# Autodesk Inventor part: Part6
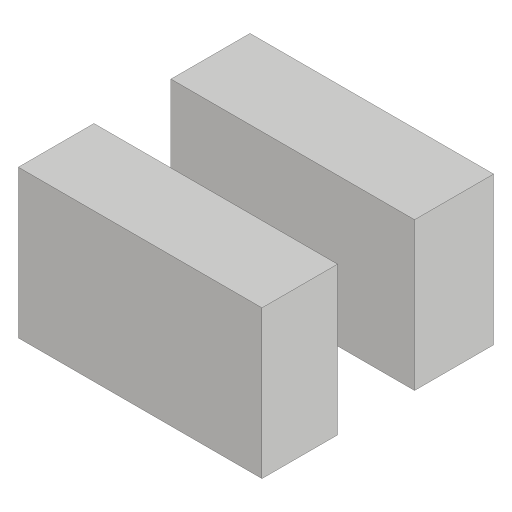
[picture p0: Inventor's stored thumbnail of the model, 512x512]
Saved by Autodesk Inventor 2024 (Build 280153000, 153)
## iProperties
Created: 2015-07
Part Number: Part6
Material: Generic
Document SubType Name: Modeling
Designer: Sandeep
Density: 1 g/cm^3
Appearance: Default
Author: Sandeep
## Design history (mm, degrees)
sketch "Sketch1"
  geometry: L1 (-17.042, 14.133)-(12.609, 14.133); L2 (12.609, 14.133)-(12.609, -14.063); L3 (12.609, -14.063)-(-17.042, -14.063); L4 (-17.042, -14.063)-(-17.042, 14.133); 1 further point
  constraints: 8 end point, 2 parallel, 1 horizontal, 1 perpendicular
extrude "Extrusion1" new body sketch "Sketch1" distance "d0" = 18; taper "d1" = 0 deg
sketch "Sketch2"
  geometry: L1 (-18, 28.196)-(-18, 0) reference; L2 (-18, 9.203)-(0.196, 9.203); L3 (0.196, 9.203)-(0.196, 18.574); L4 (0.196, 18.574)-(-18, 18.574); L5 (-18, 18.574)-(-18, 9.203); 1 further point
  constraints: 8 end point, 2 parallel, 1 horizontal, 1 perpendicular, 1 point on line
extrude "Extrusion2" cut sketch "Sketch2" distance "d2" = 8; taper "d3" = 0 deg
node "Direct Edit1"
body "Solid1"
feature "Delete1"
